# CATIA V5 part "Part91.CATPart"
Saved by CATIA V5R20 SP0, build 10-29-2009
Part number: FA 063200-2 - comprimido
Revision: ANY
Definition: UNKNOWN
Nomenclature: FA 063200-2 - comprimido
Source: Unknown
Bounding box of the stored display mesh (mm): x -1.95 to 1.95, y 0 to 5.85, z -1.95 to 1.95
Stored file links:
  C:\Users\Utente\Desktop\IO LAVORO\3D X SITO CF\CUMSA\3D files FA\FA 063200\Part91.CATPart

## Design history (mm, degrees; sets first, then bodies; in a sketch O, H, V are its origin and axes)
Body1 "Cortar-Extruir1" (main body)
  Solid1: solid without history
